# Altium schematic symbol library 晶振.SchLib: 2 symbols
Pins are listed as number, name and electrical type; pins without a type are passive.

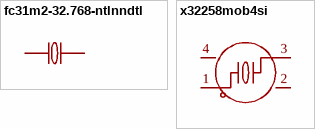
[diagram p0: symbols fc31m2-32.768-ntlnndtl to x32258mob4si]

## fc31m2-32.768-ntlnndtl
designator U??  (value not drawn)
晶振类型:贴片晶振;频率:32.768kHz;常温频差:±10ppm;负载电容:12.5pF;频率稳定度:±10ppm;; Manufacturer: HCI(杭晶); AddInBom: yes; ModelId: 762d7afc596f4558a373612390f4386d; ModelName: CRYSTAL-SMD_L3.2-W1.5-1; ModelTransform: 125.984,59.055,0,0,0,0,0,0,0; Normal temperature Frequency Tolerance: ±10ppm; Load Capacitance: 12.5pF; Equivalent Series Resistance(ESR): 70kΩ
footprint CRYSTAL-SMD_L3.2-W1.5
pins: 1, 2

## x32258mob4si
designator X??  (value not drawn)
晶振类型:贴片晶振;频率:8MHz;常温频差:±10ppm;负载电容:12pF;频率稳定度:±20ppm;; Manufacturer: YXC(扬兴晶振); AddInBom: yes; ModelId: ff2dfd5650294453a14147960efe1838; ModelName: CRYSTAL-SMD_4P-L3.2-W2.5-BL; ModelTransform: 125.984,98.425,0,0,0,0,0,0,0; Value: 8MHz; Normal temperature Frequency Tolerance: ±10ppm; Load Capacitance: 12pF; Frequency Stability: ±20ppm; Equivalent Series Resistance(ESR): 180Ω
footprint CRYSTAL-SMD_4P-L3.2-W2.5-BL
pins: 1, 2 GND, 3, 4 GND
